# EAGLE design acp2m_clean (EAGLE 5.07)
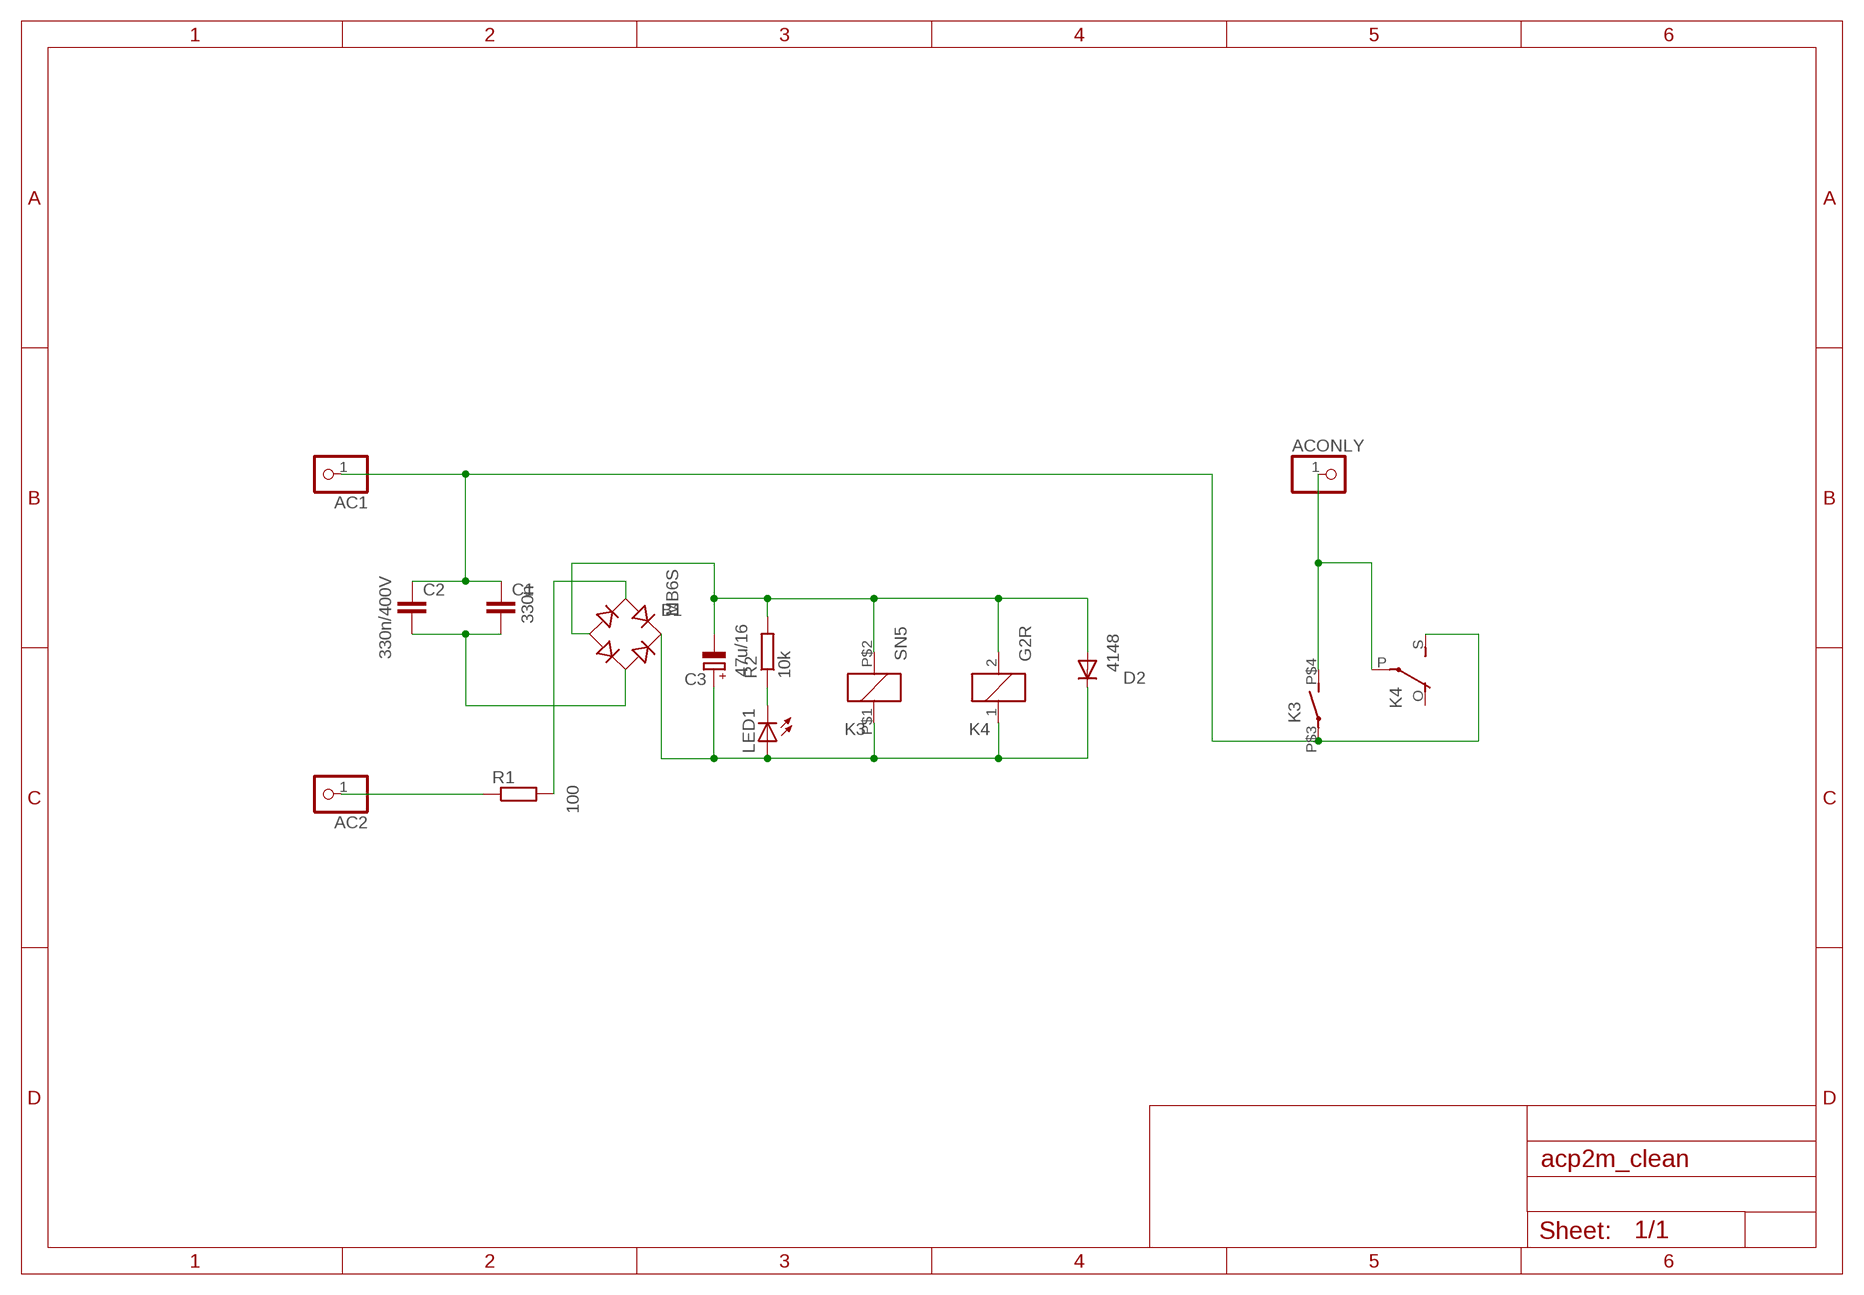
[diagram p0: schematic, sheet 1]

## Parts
AC1  PINHD-1X12MM2  [1X2MM2]
AC2  PINHD-1X12MM2  [1X2MM2]
ACONLY  PINHD-1X12MM2  [1X2MM2]
B1  MB6S  [SOIC-4]
C1  330n  C-EU150-054X183  [C150-054X183]
C2  330n/400V  C-EU102-043X133  [C102-043X133]
C3  47u/16  CPOL-EUE2.5-5  [E2,5-5]
D2  4148  1N4148MINIMELF  [MINIMELF]
K3  SN5  [HU]
K4  G2R  [G2R]
LED1  LEDSMT1206  [1206]
R1  100  R-EU_0204/5  [0204/5]
R2  10k  R-EU_R1206  [R1206]

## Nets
AC1: AC1.1 C1.1 C2.1 K3.P$3(2:P) K4.S(2:S)
AC2: AC2.1 R1.1
ACOUT: ACONLY.1 K3.P$4(2:S) K4.P(2:P)
MINUS: B1.- C3.- D2.A K3.P$2 K4.2 R2.2
N$4: LED1.C R2.1
PLUS: B1.+ C3.+ D2.C K3.P$1 K4.1 LED1.A
RAC1: B1.~2(AC2) C1.2 C2.2
RAC2: B1.~1(AC1) R1.2
Unconnected: K4.O(2:O)

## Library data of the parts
AC1 AC2 ACONLY = pinhead:PINHD-1X1: PIN HEADER
B1 = rectifier:MB*S: Bridge Rectifier Source: http://www.fairchildsemi.com/ds/MB/MB6S.pdf
C1 C2 = rcl:C-EU: CAPACITOR, European symbol
C3 = rcl:CPOL-EU: POLARIZED CAPACITOR, European symbol
D2 = diode-1:1N4148: DIODE
K3 = relay:SN*: Slim PCB Relay 1 pole 6 A SCHRACK Source: http://www.schrack.com/.. 5815.pdf
K4 = relay:G2R: RELAY 1 x switch, Omron
LED1 = led:LED: LED
R1 R2 = rcl:R-EU_: RESISTOR, European symbol

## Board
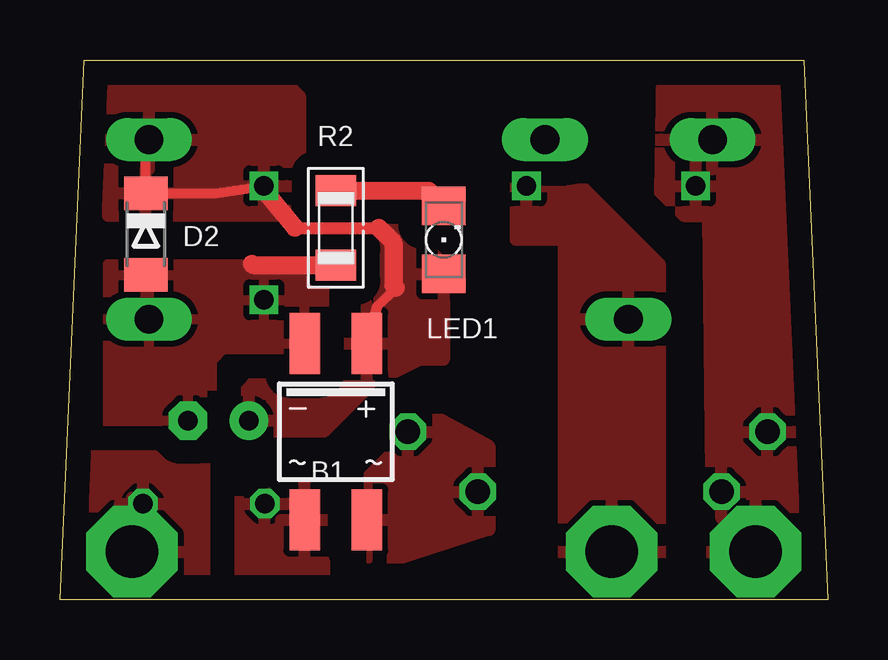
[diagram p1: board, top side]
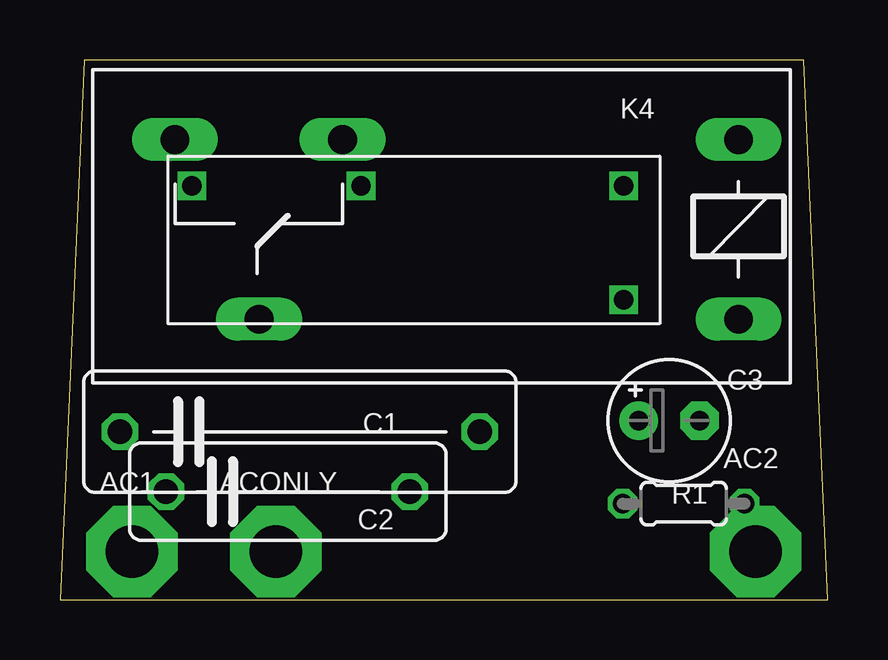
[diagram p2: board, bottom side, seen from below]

Size 32 x 22.5 mm. Coordinates in mm from the lower left corner, seen from the top.
Outline: 32,0 0,0 1,22.5 31,22.5 32,0
Copper layers (1*16): Top 0.035mm / dielectric 1.5mm / Bottom 0.035mm
Design rules "default *": minimum track width 10mil, minimum drill 20mil, track to track 8mil, track to pad 8mil, pad to pad 8mil, via to via 8mil, smd to smd 8mil, copper to edge 40mil, drill to drill 8mil, minimum pad ring 1mil, minimum via ring 8mil, stop-mask expansion 4mil, vias tented up to drill 0mil, thermal gap 10mil

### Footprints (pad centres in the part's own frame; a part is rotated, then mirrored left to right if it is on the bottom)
1X2MM2 = drill 2.2 pad 3.81 octagon: 1 0,0
SOIC-4 = smd 1.27 x 2.54: + 1.3,3.685; - -1.3,3.685; ~1 -1.3,-3.685; ~2 1.3,-3.685
C150-054X183 = drill 1.016 octagon: 1 -7.493,0; 2 7.493,0
C102-043X133 = drill 1.016 octagon: 1 -5.08,0; 2 5.08,0
E2,5-5 = drill 0.813 pad 1.6 round: + -1.27,0 | drill 0.813 pad 1.6 octagon: - 1.27,0
MINIMELF = smd 1.4 x 1.8: A 1.7,0; C -1.7,0
HU = drill 0.8 square: P$1 2.25,-9; P$2 -2.5,-9; P$3 2.25,9; P$4 2.25,1.95
G2R = drill 1.2 pad 1.778 long: 1 -2.54,-3.683; 2 -2.54,3.81; O 13.97,-3.683; P 17.45,3.81; S 20.955,-3.683
1206 = smd 1.6 x 1.803: A -1.422,0; C 1.422,0
0204/5 = drill 0.813 octagon: 1 -2.54,0; 2 2.54,0
R1206 = smd 1.3 x 1.7: 1 -1.55,0; 2 1.55,0

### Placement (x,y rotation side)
AC1  29,2 0 bottom
AC2  3,2 0 bottom
ACONLY  23,2 0 bottom
B1  11.5,7 0 top
C1  22,7 0 bottom
C2  22.5,4.5 0 bottom
C3  6.61,7.46 0 bottom
D2  3.58,15.24 270 top
K3  17.5,15 90 bottom
K4  6.25,15.5 180 bottom
LED1  16,15 90 top
R1  6,4 180 bottom
R2  11.5,15.5 270 top

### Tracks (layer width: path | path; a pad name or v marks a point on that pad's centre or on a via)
AC1
  pour Top (isolate 0.813): 30.3,22 25.1,22 25,17 26,16 27,16 27.2,-0.2 29,0 31,4 31.2,21.6
AC2
  pour Top (isolate 1): 1,6 6,6 6,0 1,0
ACOUT
  pour Top (isolate 1): 19,18 21,18 25,14 25,0 21,0 21,15 19,15
MINUS
  Top 0.75: R2.2 8.05,13.95 8,14
  pour Top (isolate 1, rank 3): 2,14 11,14 11,10 10,9 8,9 6,7 2,7
N$4
  Top 0.75: R2.1 15.37,17.05 LED1.C
PLUS
  Top 0.406: K4.1 3.58,19.28 D2.C 6.5,16.94 K3.P$1 8.5,17.05 | 13.21,10.21 B1.+ 13.21,12.21 14,13
  Top 0.5: 9.8,15.5 13.3,15.5
  Top 0.75: 8.5,17.05 9.8,15.5 | 13.3,15.5 13.9,14.9 13.9,13.1 14,13
  pour Top (isolate 1, rank 2): 7,7 7,8 8,9 11,9 12,10 12,14 10,16 2,16 2,22 9,22 10,21 10,17 11,16 14,16 16,14 16,10 15,10 13,9 11,7
RAC1
  pour Top (isolate 1.5, rank 3): 12,6 14,8 15,8 17.9,6.4 17.9,2.9 12,1
RAC2
  pour Top (isolate 1, rank 2): 7,4 11,5 11,0 7,0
